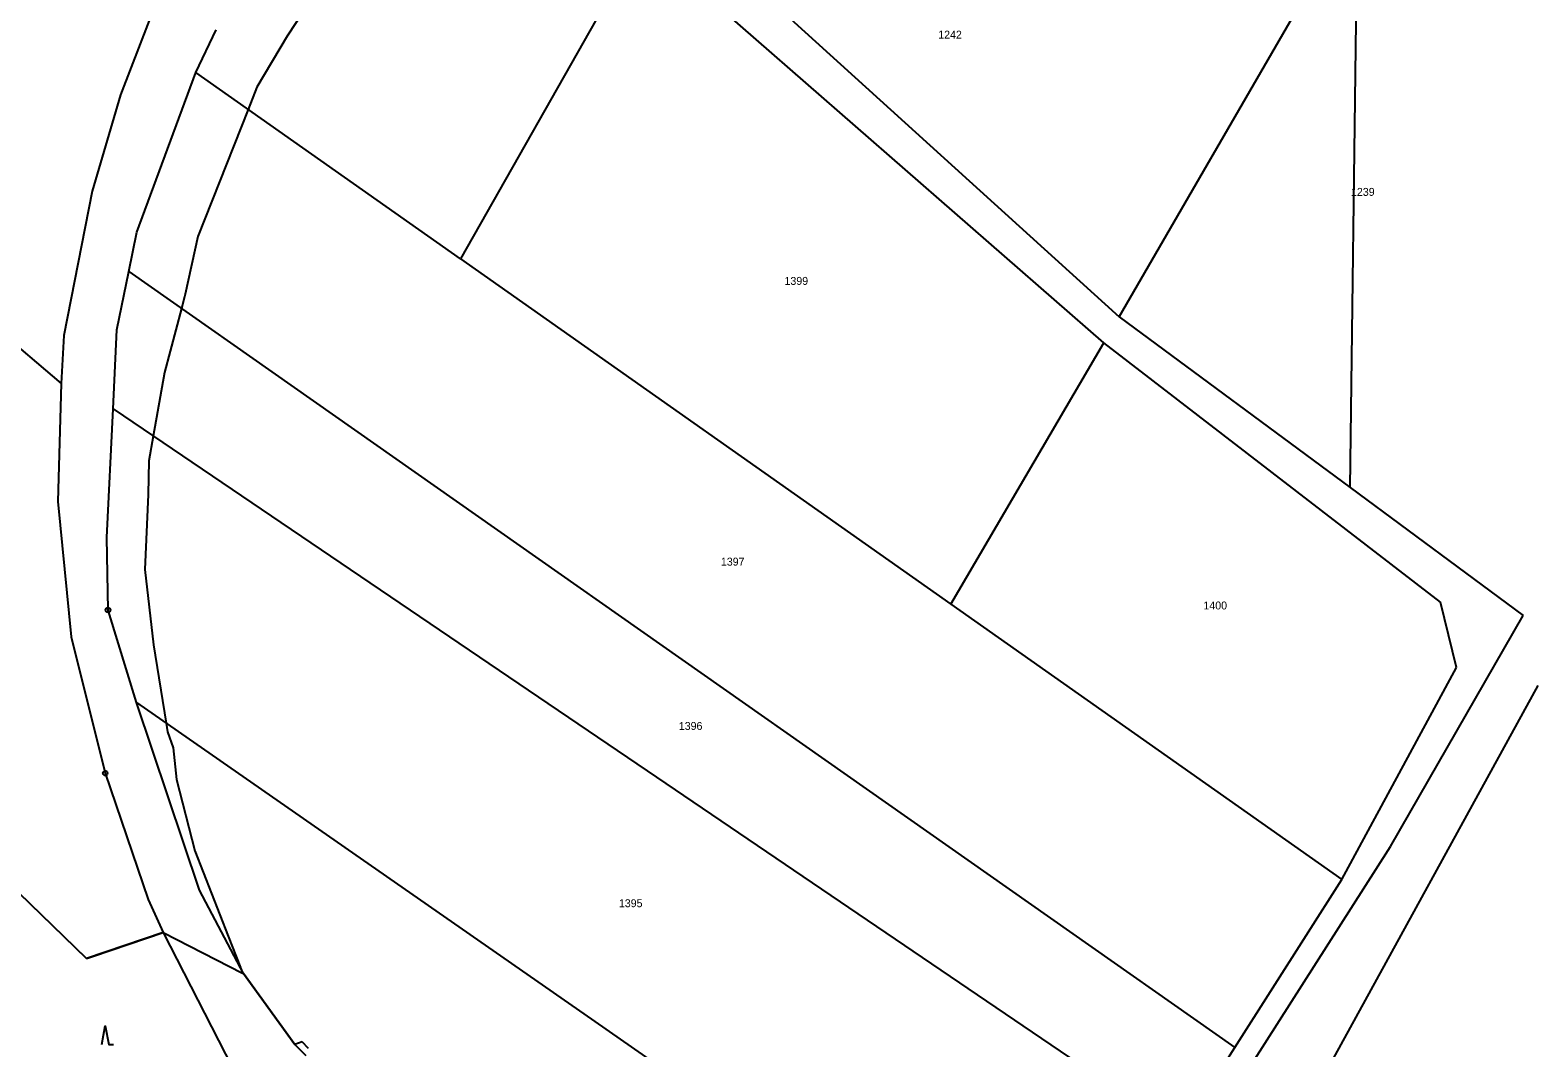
# Model space of a CAD drawing. Extents: x -792913 to -792113, y -1112764 to -1111548.
# Drawn here: x -792595.9 to -792273.1, y -1112161.5 to -1111943.5 of the extents above; entities that cross this region are included whole.
import ezdxf

# ---------------------------------------------------------------- set-up
doc = ezdxf.new("R2010")
doc.units = 0
for name, color, linetype in [('Vrstva 1', 7, 'Continuous'), ('Vrstva 11', 7, 'Continuous'), ('Vrstva 2', 7, 'Continuous'), ('Vrstva 3', 7, 'Continuous'), ('Vrstva 8', 7, 'Continuous')]:
    doc.layers.add(name, color=color, linetype=linetype)

msp = doc.modelspace()

# ---------------------------------------------------------------- linework, layer by layer
at = {"layer": 'Vrstva 1'}
for p, q in [((-792313.3, -1112041.43), (-792311.65, -1111916.52)), ((-792362.71, -1112004.87), (-792313.71, -1111920.09)), ((-792454.87, -1111921.31), (-792362.71, -1112004.87)), ((-792464.99, -1111924), (-792503.77, -1111992.47)), ((-792365.99, -1112010.44), (-792464.99, -1111924)), ((-792568.49, -1111936.3), (-792576.6, -1111957.32)), ((-792560.46, -1111952.54), (-792556.1, -1111943.37)), ((-792671.11, -1111949.58), (-792589.25, -1112019.19)), ((-792573.11, -1111986.72), (-792560.46, -1111952.54)), ((-792503.77, -1111992.47), (-792560.46, -1111952.54)), ((-792576.6, -1111957.32), (-792582.66, -1111977.99)), ((-792582.66, -1111977.99), (-792588.72, -1112008.87)), ((-792574.81, -1111995.15), (-792573.11, -1111986.72)), ((-792503.77, -1111992.47), (-792398.77, -1112066.43)), ((-792577.34, -1112007.69), (-792574.81, -1111995.15)), ((-792574.81, -1111995.15), (-792456.39, -1112078.27)), ((-792362.71, -1112004.87), (-792313.3, -1112041.43)), ((-792588.72, -1112008.87), (-792589.25, -1112019.19)), ((-792578.14, -1112024.63), (-792577.34, -1112007.69)), ((-792398.77, -1112066.43), (-792365.99, -1112010.44)), ((-792293.95, -1112066.03), (-792365.99, -1112010.44)), ((-792589.25, -1112019.19), (-792590.02, -1112044.46)), ((-792579.47, -1112052.18), (-792578.14, -1112024.63)), ((-792578.14, -1112024.63), (-792463.83, -1112102.18)), ((-792313.3, -1112041.43), (-792276.21, -1112068.88)), ((-792590.02, -1112044.46), (-792587.12, -1112073.48)), ((-792579.25, -1112067.71), (-792579.47, -1112052.18)), ((-792573.16, -1112087.55), (-792579.25, -1112067.71)), ((-792398.77, -1112066.43), (-792315.03, -1112125.41)), ((-792290.47, -1112080), (-792293.95, -1112066.03)), ((-792304.62, -1112118.38), (-792276.21, -1112068.88)), ((-792276.21, -1112068.88), (-792276.21, -1112068.88)), ((-792587.12, -1112073.48), (-792579.84, -1112102.67)), ((-792456.39, -1112078.27), (-792337.97, -1112161.4)), ((-792315.03, -1112125.41), (-792290.47, -1112080)), ((-792273.08, -1112083.84), (-792323.32, -1112175.38)), ((-792273.08, -1112083.84), (-792273.08, -1112083.84)), ((-792273.08, -1112083.84), (-792273.08, -1112083.84)), ((-792573.16, -1112087.55), (-792475.03, -1112155.83)), ((-792559.63, -1112127.72), (-792573.16, -1112087.55)), ((-792583.87, -1112142.36), (-792623.73, -1112103.69)), ((-792579.84, -1112102.67), (-792570.65, -1112129.69)), ((-792463.83, -1112102.18), (-792349.52, -1112179.73)), ((-792343.98, -1112180.01), (-792304.62, -1112118.38)), ((-792337.97, -1112161.4), (-792315.03, -1112125.41)), ((-792570.65, -1112129.69), (-792567.46, -1112136.79)), ((-792550.22, -1112145.58), (-792559.63, -1112127.72)), ((-792567.46, -1112136.79), (-792583.87, -1112142.36)), ((-792567.46, -1112136.79), (-792551.14, -1112168.59)), ((-792539.26, -1112160.8), (-792550.22, -1112145.58)), ((-792475.03, -1112155.83), (-792376.89, -1112224.11)), ((-792537.7, -1112160.18), (-792539.26, -1112160.8)), ((-792536.31, -1112161.61), (-792537.7, -1112160.18)), ((-792349.52, -1112179.73), (-792337.97, -1112161.4))]:
    msp.add_line(p, q, dxfattribs=at)
at = {"layer": 'Vrstva 11'}
for p, q in [((-792530.98, -1111929.67), (-792540.9, -1111944.78)), ((-792540.9, -1111944.78), (-792547.37, -1111955.7)), ((-792547.37, -1111955.7), (-792549.24, -1111960.44)), ((-792549.24, -1111960.44), (-792560.02, -1111987.71)), ((-792560.02, -1111987.71), (-792562.73, -1112000)), ((-792562.86, -1112000.59), (-792563.52, -1112003.08)), ((-792562.73, -1112000), (-792562.86, -1112000.59)), ((-792563.52, -1112003.08), (-792567.14, -1112016.8)), ((-792567.14, -1112016.8), (-792569.55, -1112030.46)), ((-792569.55, -1112030.46), (-792570.48, -1112035.77)), ((-792570.48, -1112035.77), (-792570.62, -1112042.96)), ((-792570.62, -1112042.96), (-792571.35, -1112059.02)), ((-792571.35, -1112059.02), (-792569.54, -1112075.13)), ((-792569.54, -1112075.13), (-792566.81, -1112091.97)), ((-792273.08, -1112083.84), (-792273.08, -1112083.84)), ((-792566.81, -1112091.97), (-792566.51, -1112093.81)), ((-792566.51, -1112093.81), (-792565.3, -1112097.22)), ((-792565.3, -1112097.22), (-792564.58, -1112104.01)), ((-792623.73, -1112103.69), (-792583.87, -1112142.36)), ((-792564.58, -1112104.01), (-792560.63, -1112119.32)), ((-792560.63, -1112119.32), (-792553.5, -1112137.61)), ((-792582.33, -1112141.83), (-792567.46, -1112136.79)), ((-792567.46, -1112136.79), (-792550.44, -1112145.47)), ((-792553.5, -1112137.61), (-792550.9, -1112144.29)), ((-792583.87, -1112142.36), (-792582.33, -1112141.83)), ((-792550.9, -1112144.29), (-792550.87, -1112144.36)), ((-792550.87, -1112144.36), (-792550.68, -1112144.84)), ((-792550.68, -1112144.84), (-792550.44, -1112145.47)), ((-792550.44, -1112145.47), (-792550.22, -1112145.58)), ((-792550.22, -1112145.58), (-792539.26, -1112160.8)), ((-792539.26, -1112160.8), (-792536.88, -1112163.17))]:
    msp.add_line(p, q, dxfattribs=at)
at = {"layer": 'Vrstva 3'}
msp.add_lwpolyline([(-792580.58, -1112160.81), (-792579.83, -1112156.81), (-792579.08, -1112160.81), (-792578.08, -1112160.81)], dxfattribs=at)
at = {"layer": 'Vrstva 8'}
for p, q in [((-792579.37, -1112067.71), (-792579.13, -1112067.71)), ((-792579.96, -1112102.67), (-792579.72, -1112102.67))]:
    msp.add_line(p, q, dxfattribs=at)
for points in [[(-792579.1, -1112067.23), (-792578.85, -1112067.41), (-792578.75, -1112067.7), (-792578.85, -1112067.99), (-792579.1, -1112068.17), (-792579.41, -1112068.17), (-792579.66, -1112067.99), (-792579.76, -1112067.7), (-792579.66, -1112067.41), (-792579.41, -1112067.23)], [(-792579.69, -1112102.19), (-792579.44, -1112102.37), (-792579.34, -1112102.66), (-792579.44, -1112102.95), (-792579.69, -1112103.13), (-792580, -1112103.13), (-792580.25, -1112102.95), (-792580.35, -1112102.66), (-792580.25, -1112102.37), (-792580, -1112102.19)]]:
    msp.add_lwpolyline(points, close=True, dxfattribs=at)

# ---------------------------------------------------------------- texts
at = {"layer": 'Vrstva 2'}
for s, p in [('1242', (-792401.477, -1111945.29)), ('1239', (-792313.087, -1111978.97)), ('1399', (-792434.397, -1111998.04)), ('1397', (-792448.017, -1112058.19)), ('1400', (-792344.687, -1112067.58)), ('1396', (-792457.027, -1112093.39)), ('1395', (-792469.857, -1112131.37))]:
    msp.add_text(s, height=1.7, dxfattribs=at).set_placement(p)

doc.saveas('drawing.dxf')
